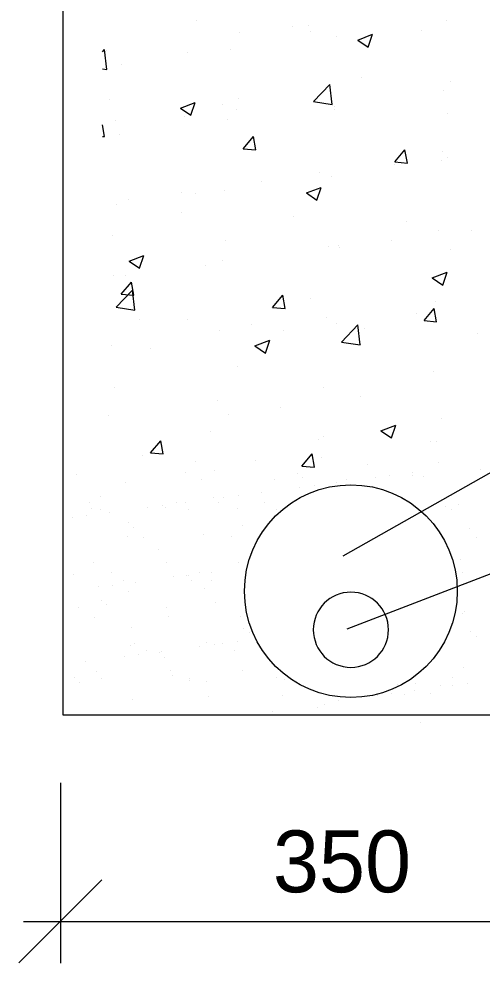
# Model space of a CAD drawing. Extents: x -480568.5 to -480543.1, y -1126945.4 to -1126930.6.
# Drawn here: x -480566.226 to -480565.436, y -1126940.514 to -1126938.902 of the extents above; entities that cross this region are included whole.
import ezdxf

# ---------------------------------------------------------------- set-up
doc = ezdxf.new("R2010")
doc.units = 0
doc.layers.add('ELEKTRO', color=7, linetype='Continuous')

msp = doc.modelspace()

# ---------------------------------------------------------------- linework, layer by layer
at = {"layer": 'ELEKTRO'}
for p, q in [((-480566.1515, -1126937.2869), (-480566.1515, -1126940.0897)), ((-480565.9241, -1126938.9053), (-480565.9241, -1126938.9053)), ((-480565.4974, -1126938.9047), (-480565.4974, -1126938.9047)), ((-480565.7597, -1126938.9146), (-480565.7597, -1126938.9146)), ((-480565.732, -1126938.9134), (-480565.732, -1126938.9134)), ((-480565.5398, -1126938.9215), (-480565.5398, -1126938.9215)), ((-480565.8498, -1126938.9264), (-480565.8498, -1126938.9264)), ((-480565.7282, -1126938.9238), (-480565.7282, -1126938.9238)), ((-480565.6844, -1126938.9317), (-480565.6844, -1126938.9317)), ((-480565.6484, -1126938.9384), (-480565.6232, -1126938.9287)), ((-480565.6305, -1126938.9505), (-480565.6232, -1126938.9287)), ((-480565.6484, -1126938.9384), (-480565.6305, -1126938.9505)), ((-480566.0838, -1126938.9586), (-480566.08, -1126938.9547)), ((-480566.0761, -1126938.9889), (-480566.08, -1126938.9547)), ((-480566.0771, -1126938.9564), (-480566.0771, -1126938.9564)), ((-480565.9381, -1126938.9599), (-480565.9381, -1126938.9599)), ((-480565.8662, -1126938.9548), (-480565.8662, -1126938.9548)), ((-480566.051, -1126938.9801), (-480566.051, -1126938.9801)), ((-480566.0838, -1126938.9877), (-480566.0761, -1126938.9889)), ((-480565.7239, -1126939.0435), (-480565.6958, -1126939.0143)), ((-480565.6918, -1126939.0485), (-480565.6958, -1126939.0143)), ((-480565.6419, -1126939.0029), (-480565.6419, -1126939.0029)), ((-480565.4907, -1126939.0087), (-480565.4907, -1126939.0087)), ((-480565.5017, -1126939.0246), (-480565.5017, -1126939.0246)), ((-480566.0717, -1126939.0399), (-480566.0717, -1126939.0399)), ((-480565.9508, -1126939.0545), (-480565.9256, -1126939.0448)), ((-480565.9329, -1126939.0666), (-480565.9256, -1126939.0448)), ((-480565.8795, -1126939.0481), (-480565.8795, -1126939.0481)), ((-480565.8518, -1126939.0389), (-480565.8518, -1126939.0389)), ((-480565.7239, -1126939.0435), (-480565.6919, -1126939.0485)), ((-480565.718, -1126939.0386), (-480565.718, -1126939.0386)), ((-480565.9508, -1126939.0545), (-480565.9329, -1126939.0666)), ((-480565.8544, -1126939.0566), (-480565.8544, -1126939.0566)), ((-480565.6887, -1126939.0516), (-480565.6887, -1126939.0516)), ((-480565.6873, -1126939.0562), (-480565.6873, -1126939.0562)), ((-480565.4951, -1126939.0643), (-480565.4951, -1126939.0643)), ((-480566.0618, -1126939.075), (-480566.0618, -1126939.075)), ((-480565.9445, -1126939.0684), (-480565.9445, -1126939.0684)), ((-480565.8706, -1126939.0746), (-480565.8706, -1126939.0746)), ((-480566.0801, -1126939.1032), (-480566.0838, -1126939.0834)), ((-480566.0838, -1126939.1029), (-480566.0801, -1126939.1032)), ((-480566.0554, -1126939.1), (-480566.0554, -1126939.1)), ((-480565.8435, -1126939.1239), (-480565.8261, -1126939.1032)), ((-480565.8219, -1126939.1258), (-480565.8261, -1126939.1032)), ((-480565.8435, -1126939.1239), (-480565.8219, -1126939.1258)), ((-480565.5852, -1126939.1465), (-480565.5679, -1126939.1258)), ((-480565.5637, -1126939.1484), (-480565.5679, -1126939.1258)), ((-480565.5044, -1126939.1289), (-480565.5044, -1126939.1289)), ((-480565.5852, -1126939.1465), (-480565.5637, -1126939.1484)), ((-480565.5061, -1126939.1444), (-480565.5061, -1126939.1444)), ((-480565.4952, -1126939.1388), (-480565.4952, -1126939.1388)), ((-480565.5854, -1126939.1507), (-480565.5854, -1126939.1507)), ((-480565.7144, -1126939.1649), (-480565.7144, -1126939.1649)), ((-480565.6931, -1126939.1714), (-480565.6931, -1126939.1714)), ((-480564.5416, -1126939.1799), (-480565.6738, -1126939.819)), ((-480565.8749, -1126939.1945), (-480565.8749, -1126939.1945)), ((-480565.8127, -1126939.1806), (-480565.8127, -1126939.1806)), ((-480565.736, -1126939.1994), (-480565.7108, -1126939.1898)), ((-480565.7181, -1126939.2115), (-480565.7108, -1126939.1898)), ((-480566.0392, -1126939.2104), (-480566.0392, -1126939.2104)), ((-480565.9491, -1126939.1986), (-480565.9491, -1126939.1986)), ((-480565.9243, -1126939.201), (-480565.9243, -1126939.201)), ((-480565.736, -1126939.1994), (-480565.7181, -1126939.2115)), ((-480566.0598, -1126939.2198), (-480566.0598, -1126939.2198)), ((-480565.9496, -1126939.232), (-480565.9496, -1126939.232)), ((-480565.7574, -1126939.2401), (-480565.7574, -1126939.2401)), ((-480565.5652, -1126939.2483), (-480565.5652, -1126939.2483)), ((-480566.0659, -1126939.2723), (-480566.0659, -1126939.2723)), ((-480565.5105, -1126939.2643), (-480565.5105, -1126939.2643)), ((-480565.4536, -1126939.2628), (-480565.4536, -1126939.2628)), ((-480565.8737, -1126939.2804), (-480565.8737, -1126939.2804)), ((-480565.6975, -1126939.2913), (-480565.6975, -1126939.2913)), ((-480565.6815, -1126939.2885), (-480565.6815, -1126939.2885)), ((-480565.6801, -1126939.2927), (-480565.6801, -1126939.2927)), ((-480565.5899, -1126939.2808), (-480565.5899, -1126939.2808)), ((-480566.0384, -1126939.3156), (-480566.0132, -1126939.3059)), ((-480566.0205, -1126939.3276), (-480566.0132, -1126939.3059)), ((-480565.4893, -1126939.2966), (-480565.4893, -1126939.2966)), ((-480566.0384, -1126939.3156), (-480566.0205, -1126939.3276)), ((-480565.9074, -1126939.3226), (-480565.9074, -1126939.3226)), ((-480565.8793, -1126939.3143), (-480565.8793, -1126939.3143)), ((-480566.0642, -1126939.3396), (-480566.0642, -1126939.3396)), ((-480566.0438, -1126939.3405), (-480566.0438, -1126939.3405)), ((-480565.5211, -1126939.3444), (-480565.4959, -1126939.3347)), ((-480565.5032, -1126939.3565), (-480565.4959, -1126939.3347)), ((-480566.0517, -1126939.3721), (-480566.0344, -1126939.3514)), ((-480566.0302, -1126939.374), (-480566.0344, -1126939.3514)), ((-480565.5211, -1126939.3444), (-480565.5032, -1126939.3565)), ((-480565.5193, -1126939.3437), (-480565.5193, -1126939.3437)), ((-480566.0604, -1126939.3942), (-480566.0323, -1126939.365)), ((-480566.0517, -1126939.3721), (-480566.0302, -1126939.374)), ((-480566.0283, -1126939.3992), (-480566.0323, -1126939.365)), ((-480565.7935, -1126939.3947), (-480565.7761, -1126939.374)), ((-480565.772, -1126939.3966), (-480565.7761, -1126939.374)), ((-480565.7292, -1126939.3797), (-480565.7292, -1126939.3797)), ((-480565.5149, -1126939.3841), (-480565.5149, -1126939.3841)), ((-480566.0604, -1126939.3942), (-480566.0283, -1126939.3992)), ((-480565.7935, -1126939.3947), (-480565.772, -1126939.3966)), ((-480565.5483, -1126939.4048), (-480565.5483, -1126939.4048)), ((-480565.5353, -1126939.4173), (-480565.5179, -1126939.3966)), ((-480565.5138, -1126939.4192), (-480565.5179, -1126939.3966)), ((-480566.0212, -1126939.415), (-480566.0212, -1126939.415)), ((-480565.9392, -1126939.4157), (-480565.9392, -1126939.4157)), ((-480565.7019, -1126939.4111), (-480565.7019, -1126939.4111)), ((-480565.5353, -1126939.4173), (-480565.5138, -1126939.4192)), ((-480565.8837, -1126939.4341), (-480565.8837, -1126939.4341)), ((-480565.829, -1126939.4231), (-480565.829, -1126939.4231)), ((-480565.7748, -1126939.4347), (-480565.7748, -1126939.4347)), ((-480565.6846, -1126939.4228), (-480565.6846, -1126939.4228)), ((-480565.6761, -1126939.4538), (-480565.6481, -1126939.4246)), ((-480565.6441, -1126939.4588), (-480565.6481, -1126939.4246)), ((-480565.6369, -1126939.4313), (-480565.6369, -1126939.4313)), ((-480565.8236, -1126939.4605), (-480565.7984, -1126939.4508)), ((-480565.8056, -1126939.4726), (-480565.7983, -1126939.4508)), ((-480565.6761, -1126939.4538), (-480565.6441, -1126939.4588)), ((-480565.4447, -1126939.4394), (-480565.4447, -1126939.4394)), ((-480566.0685, -1126939.4595), (-480566.0685, -1126939.4595)), ((-480566.0021, -1126939.4646), (-480566.0021, -1126939.4646)), ((-480565.8236, -1126939.4605), (-480565.8056, -1126939.4726)), ((-480565.643, -1126939.4588), (-480565.643, -1126939.4588)), ((-480565.8529, -1126939.4948), (-480565.8529, -1126939.4948)), ((-480564.5183, -1126939.501), (-480565.6669, -1126939.9436)), ((-480565.5193, -1126939.5039), (-480565.5193, -1126939.5039)), ((-480566.0628, -1126939.5308), (-480566.0628, -1126939.5308)), ((-480565.7062, -1126939.5309), (-480565.7062, -1126939.5309)), ((-480565.643, -1126939.5468), (-480565.643, -1126939.5468)), ((-480565.8881, -1126939.554), (-480565.8881, -1126939.554)), ((-480565.7794, -1126939.5648), (-480565.7794, -1126939.5648)), ((-480566.0729, -1126939.5793), (-480566.0729, -1126939.5793)), ((-480565.8695, -1126939.5766), (-480565.8695, -1126939.5766)), ((-480565.6087, -1126939.6054), (-480565.5835, -1126939.5958)), ((-480565.5908, -1126939.6175), (-480565.5835, -1126939.5958)), ((-480565.5055, -1126939.5847), (-480565.5055, -1126939.5847)), ((-480565.8991, -1126939.6071), (-480565.8991, -1126939.6071)), ((-480565.6087, -1126939.6054), (-480565.5908, -1126939.6175)), ((-480566.0018, -1126939.6429), (-480565.9844, -1126939.6222)), ((-480565.9802, -1126939.6448), (-480565.9844, -1126939.6222)), ((-480565.7154, -1126939.6208), (-480565.7154, -1126939.6208)), ((-480565.707, -1126939.6152), (-480565.707, -1126939.6152)), ((-480565.5236, -1126939.6238), (-480565.5236, -1126939.6238)), ((-480565.5148, -1126939.6233), (-480565.5148, -1126939.6233)), ((-480566.0154, -1126939.6473), (-480566.0154, -1126939.6473)), ((-480566.0018, -1126939.6429), (-480565.9802, -1126939.6448)), ((-480565.7436, -1126939.6655), (-480565.7262, -1126939.6448)), ((-480565.722, -1126939.6674), (-480565.7262, -1126939.6448)), ((-480565.9254, -1126939.6568), (-480565.9254, -1126939.6568)), ((-480565.8232, -1126939.6554), (-480565.8232, -1126939.6554)), ((-480565.7106, -1126939.6508), (-480565.7106, -1126939.6508)), ((-480565.5104, -1126939.6589), (-480565.5104, -1126939.6589)), ((-480565.9426, -1126939.6759), (-480565.9426, -1126939.6759)), ((-480565.8925, -1126939.6738), (-480565.8925, -1126939.6738)), ((-480565.7506, -1126939.6776), (-480565.7506, -1126939.6776)), ((-480565.7436, -1126939.6655), (-480565.722, -1126939.6674)), ((-480565.6311, -1126939.6636), (-480565.6311, -1126939.6636)), ((-480565.5546, -1126939.6768), (-480565.5546, -1126939.6768)), ((-480565.4389, -1126939.6717), (-480565.4389, -1126939.6717)), ((-480566.1287, -1126939.6798), (-480566.1287, -1126939.6798)), ((-480566.0448, -1126939.6939), (-480566.0448, -1126939.6939)), ((-480565.9151, -1126939.6892), (-480565.9151, -1126939.6892)), ((-480565.7895, -1126939.6876), (-480565.7895, -1126939.6876)), ((-480565.7417, -1126939.6857), (-480565.7417, -1126939.6857)), ((-480565.6838, -1126939.6938), (-480565.6838, -1126939.6938)), ((-480565.6667, -1126939.6882), (-480565.6667, -1126939.6882)), ((-480565.6186, -1126939.6852), (-480565.6186, -1126939.6852)), ((-480565.5937, -1126939.6819), (-480565.5937, -1126939.6819)), ((-480565.5557, -1126939.6818), (-480565.5557, -1126939.6818)), ((-480565.537, -1126939.6836), (-480565.537, -1126939.6836)), ((-480565.813, -1126939.7108), (-480565.813, -1126939.7108)), ((-480565.7478, -1126939.7022), (-480565.7478, -1126939.7022)), ((-480565.7229, -1126939.6989), (-480565.7229, -1126939.6989)), ((-480566.1065, -1126939.7274), (-480566.1065, -1126939.7274)), ((-480566.0869, -1126939.718), (-480566.0869, -1126939.718)), ((-480565.9571, -1126939.7271), (-480565.9571, -1126939.7271)), ((-480565.9422, -1126939.7278), (-480565.9422, -1126939.7278)), ((-480565.8948, -1126939.7197), (-480565.8948, -1126939.7197)), ((-480565.886, -1126939.7278), (-480565.886, -1126939.7278)), ((-480565.8771, -1126939.7192), (-480565.8771, -1126939.7192)), ((-480565.8521, -1126939.7159), (-480565.8521, -1126939.7159)), ((-480565.8076, -1126939.7268), (-480565.8076, -1126939.7268)), ((-480565.5086, -1126939.7263), (-480565.5086, -1126939.7263)), ((-480565.5079, -1126939.7256), (-480565.5079, -1126939.7256)), ((-480566.1027, -1126939.7383), (-480566.1027, -1126939.7383)), ((-480566.0863, -1126939.7403), (-480566.0863, -1126939.7403)), ((-480566.0063, -1126939.7362), (-480566.0063, -1126939.7362)), ((-480565.9813, -1126939.7329), (-480565.9813, -1126939.7329)), ((-480565.977, -1126939.7367), (-480565.977, -1126939.7367)), ((-480565.9368, -1126939.74), (-480565.9368, -1126939.74)), ((-480565.8542, -1126939.7373), (-480565.8542, -1126939.7373)), ((-480565.7873, -1126939.7397), (-480565.7873, -1126939.7397)), ((-480565.499, -1126939.7337), (-480565.499, -1126939.7337)), ((-480565.4884, -1126939.7392), (-480565.4884, -1126939.7392)), ((-480565.4761, -1126939.7316), (-480565.4761, -1126939.7316)), ((-480566.1355, -1126939.7532), (-480566.1355, -1126939.7532)), ((-480566.1105, -1126939.75), (-480566.1105, -1126939.75)), ((-480566.0715, -1126939.7448), (-480566.0715, -1126939.7448)), ((-480566.0391, -1126939.7618), (-480566.0391, -1126939.7618)), ((-480566.0303, -1126939.7699), (-480566.0303, -1126939.7699)), ((-480565.8442, -1126939.7661), (-480565.8442, -1126939.7661)), ((-480565.4573, -1126939.7719), (-480565.4573, -1126939.7719)), ((-480566.0417, -1126939.7864), (-480566.0417, -1126939.7864)), ((-480566.0134, -1126939.7867), (-480566.0134, -1126939.7867)), ((-480565.9121, -1126939.7817), (-480565.9121, -1126939.7817)), ((-480565.864, -1126939.7864), (-480565.864, -1126939.7864)), ((-480565.4452, -1126939.7866), (-480565.4452, -1126939.7866)), ((-480565.9885, -1126939.8082), (-480565.9885, -1126939.8082)), ((-480565.4731, -1126939.8241), (-480565.4731, -1126939.8241)), ((-480566.0996, -1126939.8308), (-480566.0996, -1126939.8308)), ((-480565.974, -1126939.8292), (-480565.974, -1126939.8292)), ((-480565.8512, -1126939.8298), (-480565.8512, -1126939.8298)), ((-480566.1328, -1126939.8503), (-480566.1328, -1126939.8503)), ((-480566.0678, -1126939.8476), (-480566.0678, -1126939.8476)), ((-480565.962, -1126939.8547), (-480565.962, -1126939.8547)), ((-480565.9408, -1126939.852), (-480565.9408, -1126939.852)), ((-480565.937, -1126939.8514), (-480565.937, -1126939.8514)), ((-480565.9183, -1126939.8473), (-480565.9183, -1126939.8473)), ((-480565.898, -1126939.8463), (-480565.898, -1126939.8463)), ((-480565.4699, -1126939.8465), (-480565.4699, -1126939.8465)), ((-480566.0912, -1126939.8717), (-480566.0912, -1126939.8717)), ((-480566.0662, -1126939.8684), (-480566.0662, -1126939.8684)), ((-480566.0475, -1126939.8605), (-480566.0475, -1126939.8605)), ((-480566.0272, -1126939.8633), (-480566.0272, -1126939.8633)), ((-480565.9319, -1126939.8601), (-480565.9319, -1126939.8601)), ((-480565.8981, -1126939.8602), (-480565.8981, -1126939.8602)), ((-480565.4496, -1126939.8594), (-480565.4496, -1126939.8594)), ((-480566.0387, -1126939.8789), (-480566.0387, -1126939.8789)), ((-480565.9091, -1126939.8742), (-480565.9091, -1126939.8742)), ((-480566.0851, -1126939.8941), (-480566.0851, -1126939.8941)), ((-480566.0762, -1126939.9022), (-480566.0762, -1126939.9022)), ((-480565.8902, -1126939.8983), (-480565.8902, -1126939.8983)), ((-480566.1241, -1126939.9072), (-480566.1241, -1126939.9072)), ((-480565.9747, -1126939.9069), (-480565.9747, -1126939.9069)), ((-480565.4701, -1126939.9166), (-480565.4701, -1126939.9166)), ((-480565.4661, -1126939.9137), (-480565.4661, -1126939.9137)), ((-480566.0966, -1126939.9233), (-480566.0966, -1126939.9233)), ((-480565.971, -1126939.9217), (-480565.971, -1126939.9217)), ((-480565.8482, -1126939.9223), (-480565.8482, -1126939.9223)), ((-480566.0344, -1126939.9405), (-480566.0344, -1126939.9405)), ((-480565.8424, -1126939.9421), (-480565.8424, -1126939.9421)), ((-480565.8335, -1126939.9502), (-480565.8335, -1126939.9502)), ((-480565.4554, -1126939.948), (-480565.4554, -1126939.948)), ((-480566.029, -1126939.9678), (-480566.029, -1126939.9678)), ((-480565.9061, -1126939.9667), (-480565.9061, -1126939.9667)), ((-480565.8795, -1126939.9675), (-480565.8795, -1126939.9675)), ((-480565.8537, -1126939.9647), (-480565.8537, -1126939.9647)), ((-480565.4466, -1126939.9561), (-480565.4466, -1126939.9561)), ((-480566.0357, -1126939.9714), (-480566.0357, -1126939.9714)), ((-480566.0088, -1126939.9807), (-480566.0088, -1126939.9807)), ((-480565.9867, -1126939.9842), (-480565.9867, -1126939.9842)), ((-480565.9829, -1126939.9817), (-480565.9829, -1126939.9817)), ((-480565.9177, -1126939.9731), (-480565.9177, -1126939.9731)), ((-480565.8928, -1126939.9699), (-480565.8928, -1126939.9699)), ((-480565.8593, -1126939.9804), (-480565.8593, -1126939.9804)), ((-480566.1121, -1126939.9987), (-480566.1121, -1126939.9987)), ((-480566.0469, -1126939.9902), (-480566.0469, -1126939.9902)), ((-480566.022, -1126939.9869), (-480566.022, -1126939.9869)), ((-480565.9778, -1126939.9923), (-480565.9778, -1126939.9923)), ((-480566.1512, -1126940.0039), (-480566.1512, -1126940.0039)), ((-480566.0936, -1126940.0158), (-480566.0936, -1126940.0158)), ((-480565.9679, -1126940.0142), (-480565.9679, -1126940.0142)), ((-480565.8451, -1126940.0148), (-480565.8451, -1126940.0148)), ((-480565.4671, -1126940.0091), (-480565.4671, -1126940.0091)), ((-480566.131, -1126940.0264), (-480566.131, -1126940.0264)), ((-480566.0854, -1126940.0274), (-480566.0854, -1126940.0274)), ((-480565.965, -1126940.0224), (-480565.965, -1126940.0224)), ((-480565.9361, -1126940.0306), (-480565.9361, -1126940.0306)), ((-480565.9359, -1126940.0271), (-480565.9359, -1126940.0271)), ((-480565.9056, -1126940.0333), (-480565.9056, -1126940.0333)), ((-480565.7864, -1126940.0268), (-480565.7864, -1126940.0268)), ((-480565.7728, -1126940.0305), (-480565.7728, -1126940.0305)), ((-480565.4875, -1126940.0263), (-480565.4875, -1126940.0263)), ((-480566.1221, -1126940.0345), (-480566.1221, -1126940.0345)), ((-480565.5806, -1126940.0386), (-480565.5806, -1126940.0386)), ((-480565.5511, -1126940.0491), (-480565.5511, -1126940.0491)), ((-480565.5491, -1126940.0365), (-480565.5491, -1126940.0365)), ((-480565.5065, -1126940.0406), (-480565.5065, -1126940.0406)), ((-480565.4859, -1126940.0406), (-480565.4859, -1126940.0406)), ((-480565.4609, -1126940.0373), (-480565.4609, -1126940.0373)), ((-480566.0327, -1126940.0639), (-480566.0327, -1126940.0639)), ((-480565.903, -1126940.0592), (-480565.903, -1126940.0592)), ((-480565.7774, -1126940.0576), (-480565.7774, -1126940.0576)), ((-480565.6803, -1126940.0662), (-480565.6803, -1126940.0662)), ((-480565.6151, -1126940.0576), (-480565.6151, -1126940.0576)), ((-480565.5901, -1126940.0543), (-480565.5901, -1126940.0543)), ((-480565.568, -1126940.055), (-480565.568, -1126940.055)), ((-480565.525, -1126940.0535), (-480565.525, -1126940.0535)), ((-480565.7165, -1126940.0766), (-480565.7165, -1126940.0766)), ((-480565.7043, -1126940.073), (-480565.7043, -1126940.073)), ((-480566.1515, -1126940.0897), (-480565.0967, -1126940.0897)), ((-480565.7945, -1126940.0848), (-480565.7945, -1126940.0848)), ((-480565.5411, -1126940.1032), (-480565.5411, -1126940.1032)), ((-480566.1556, -1126940.2061), (-480566.1556, -1126940.5136)), ((-480566.2263, -1126940.5131), (-480566.0849, -1126940.3717)), ((-480566.2187, -1126940.4424), (-480565.0351, -1126940.4424))]:
    msp.add_line(p, q, dxfattribs=at)
msp.add_circle((-480565.66, -1126939.8789), 0.1815, dxfattribs=at)
for start, end in [(0, 180), (180, 0)]:
    msp.add_arc((-480565.66, -1126939.9448), 0.0641, start, end, dxfattribs=at)

# ---------------------------------------------------------------- texts
msp.add_text('350', height=0.1056, dxfattribs=at).set_placement((-480565.793, -1126940.3928))

doc.saveas('drawing.dxf')
